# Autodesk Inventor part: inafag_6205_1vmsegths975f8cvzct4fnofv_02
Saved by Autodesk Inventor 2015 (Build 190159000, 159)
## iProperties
Company: TraceParts S.A.
Created: 2012-12
Part Number: inafag_6205_1vmsegths975f8cvzct4fnofv_02
Checked By: TraceParts S.A.
Catalog Web Link: www.traceparts.com
Document SubType Name: Modeling
Designer: TraceParts
Material: Generic
Density: 1 g/cm^3
Appearance: Default
Author: TraceParts
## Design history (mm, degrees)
feature "inafag_6205_1vmsegths975f8cvzct4fnofv"
body "Solid1"
